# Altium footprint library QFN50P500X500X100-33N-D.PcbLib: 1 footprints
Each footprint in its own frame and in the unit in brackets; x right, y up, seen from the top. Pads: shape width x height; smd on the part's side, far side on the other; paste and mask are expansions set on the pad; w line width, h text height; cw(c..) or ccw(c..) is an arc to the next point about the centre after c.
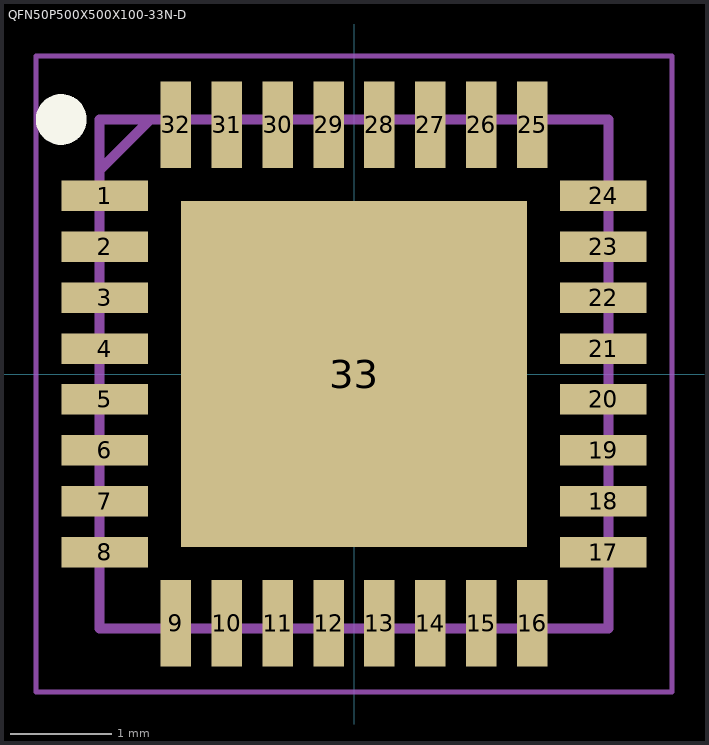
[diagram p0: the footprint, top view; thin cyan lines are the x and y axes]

## QFN50P500X500X100-33N-D [mm]
pads (33):
  rect 0.85x0.3 smd: 1(-2.45,1.75) 2(-2.45,1.25) 3(-2.45,0.75) 4(-2.45,0.25) 5(-2.45,-0.25) 6(-2.45,-0.75) 7(-2.45,-1.25) 8(-2.45,-1.75) 17(2.45,-1.75) 18(2.45,-1.25) 19(2.45,-0.75) 20(2.45,-0.25) 21(2.45,0.25) 22(2.45,0.75) 23(2.45,1.25) 24(2.45,1.75)
  rect 0.3x0.85 smd: 9(-1.75,-2.45) 10(-1.25,-2.45) 11(-0.75,-2.45) 12(-0.25,-2.45) 13(0.25,-2.45) 14(0.75,-2.45) 15(1.25,-2.45) 16(1.75,-2.45) 25(1.75,2.45) 26(1.25,2.45) 27(0.75,2.45) 28(0.25,2.45) 29(-0.25,2.45) 30(-0.75,2.45) 31(-1.25,2.45) 32(-1.75,2.45)
  rect 3.4x3.4 smd: 33(0,0)
Top Overlay:
  circle w0.25: c-2.875,2.5 r0.125
Mechanical 15:
  lines w0.1: -2.5,2 -2,2.5 ; -2.5,-2.5 2.5,-2.5 2.5,2.5 -2.5,2.5 -2.5,-2.5
Mechanical 20:
  lines w0.05: -3.125,-3.125 3.125,-3.125 3.125,3.125 -3.125,3.125 -3.125,-3.125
